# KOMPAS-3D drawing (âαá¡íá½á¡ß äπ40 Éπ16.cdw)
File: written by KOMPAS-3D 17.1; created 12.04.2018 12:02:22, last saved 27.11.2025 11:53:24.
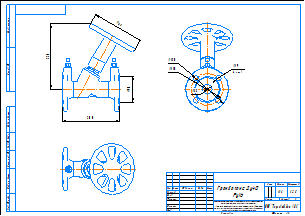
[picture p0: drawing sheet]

Sheet 1: A3, landscape

Title block, sheet 1: name: Гранбаланс Ду40 / Ру16; material: Сталь 10  ГОСТ 1050-88; mass: 11,6; sheets: 1; sheet format: A3; stored path: C:\Users\kka\KOMPAS_Work\!Trash\КМ125 КМ127 КМ225Ф Двухходовые клапана\КМ125Ф + PSL\KOMPAS 2D\Гранрег КМ125Ф Ду32 Ру16.cdw

Views: Спереди 1, Спереди, Проекционный вид 2, Проекционный вид 3
Referenced files in C:\Users\mipv\Desktop\КБЧ\Имеющиеся\: Гранбаланс Ду40 Ру16  серия 10.m3d
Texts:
  kka
  adl
  Рама для чертежей
  Лит-Масса-Масштаб
  Материал-Предприятие
  Масштаб
  Изм.
  Лист
  № докум.
  Подп.
  Дата
  Лит.
  Разраб.
  Пров.
  Т.контр.
  Листов
  Внимание! Данный продукт является объектом авторского права ООО «Торговый Дом АДЛ».
  Запрещается изменение, копирование, распространение
  (в том числе путем копирования на другие сайты и ресурсы в Интернете)
  или любое иное использование информации и объектов без предварительного
  согласия правообладателя (ООО «Торговый Дом АДЛ»).
  Н.контр.
  Утв.
  ООО "Торговый дом АДЛ"
  Изменение
  Номер документа
  Подпись
  Обозначение документа
  Наименование изделия
  Масса изделия по ГОСТ 2.109-73
  Порядковый номер листа
  Общее количество листов в документе
  Характер работы, выполненной лицом, подписавшим документ
  Наименование или индекс предприятия, выпускающего документ
  Инв. № подл.
  Подп. и дата
  Взам. инв. №
  Инв. № дубл.
  Инвентарный номер подлинника по ГОСТ 2.501-68
  Подпись принявшего подлинник в отдел технической документации
  Инвентарный номер подлинника, взамен которого выпущен данный подлинник
  Инвентарный номер дубликата по ГОСТ 2.502-68
  Подпись принявшего дубликат в отдел технической документации
  Справ. №
  Перв. примен.
  Обозначение документа, взамен или на основании которого выпущен данный документ
  Обозначение документа, в котором впервые записан данный документ
  Подпись лица, копировавшего чертеж
  Обозначение формата листа
  !Рама для чертежа
Dimensions and other numbers on the sheet: 200; 180; 228; 90; 150; 110; 35; 19; 4 отв.; 1:2,5; 1; 11,6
